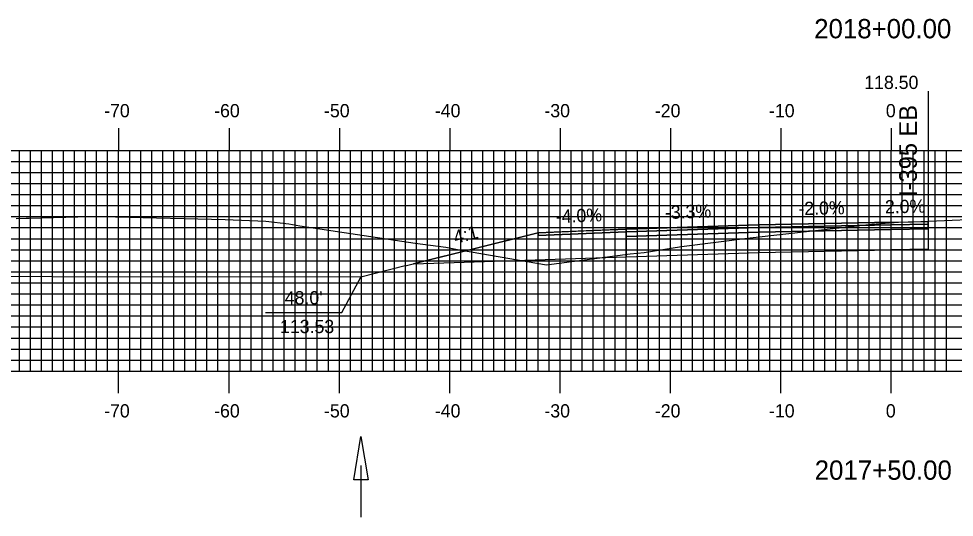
# Model space of a CAD drawing. Extents: x 855074 to 855418, y 366605 to 366825.
# Drawn here: x 855161 to 855245.8, y 366654.8 to 366700 of the extents above; entities that cross this region are included whole.
import ezdxf

# ---------------------------------------------------------------- set-up
doc = ezdxf.new("R2010")
doc.units = 0
for name, color, linetype in [('ANNOTATION', 7, 'Continuous'), ('D_Drainage_Ditch_Line', 7, 'Continuous'), ('D_Roadway_Centerline', 7, 'Continuous'), ('D_Roadway_Centerline_Text', 7, 'Continuous'), ('D_Roadway_Edge_Shoulder', 7, 'Continuous'), ('D_Roadway_Edge_TW', 7, 'Continuous'), ('D_Roadway_Pavement', 7, 'Continuous'), ('D_Roadway_SubGrade', 7, 'Continuous'), ('H_V ANNOTATION', 7, 'Continuous'), ('M_Roadway_Centerline', 7, 'Continuous'), ('MAJOR', 7, 'Continuous'), ('MINOR', 7, 'Continuous'), ('S_Roadway_Centerline', 7, 'Continuous')]:
    doc.layers.add(name, color=color, linetype=linetype)

msp = doc.modelspace()

# ---------------------------------------------------------------- linework, layer by layer
at = {"layer": 'ANNOTATION'}
msp.add_lwpolyline([(855183.363, 366673.373), (855190.292, 366673.373), (855192.022, 366676.583)], dxfattribs=at)
at = {"layer": 'D_Drainage_Ditch_Line'}
msp.add_line((855192.022, 366659.509), (855192.022, 366654.81), dxfattribs=at)
msp.add_lwpolyline([(855192.679, 366658.196), (855191.366, 366658.196), (855192.022, 366662.133)], close=True, dxfattribs=at)
at = {"layer": 'D_Roadway_Centerline'}
msp.add_lwpolyline([(855196.022, 366677.583), (855208.066, 366680.594), (855208.07, 366680.595), (855208.072, 366680.595), (855212.217, 366680.761), (855216.07, 366680.915), (855216.073, 366680.915), (855228.069, 366681.313), (855240.064, 366681.553), (855240.069, 366681.553), (855240.071, 366681.553), (855243.105, 366681.614), (855243.411, 366681.62)], dxfattribs=at)
at = {"layer": 'D_Roadway_Edge_Shoulder'}
for points in [[(855216.07, 366680.915), (855208.07, 366680.595), (855208.07, 366680.345), (855216.07, 366680.665)], [(855240.069, 366681.553), (855243.41, 366681.62), (855243.41, 366681.37), (855240.069, 366681.303)]]:
    msp.add_lwpolyline(points, close=True, dxfattribs=at)
at = {"layer": 'D_Roadway_Edge_TW'}
for points in [[(855228.069, 366681.313), (855216.07, 366680.915), (855216.07, 366680.665), (855228.069, 366681.063)], [(855240.069, 366681.553), (855228.069, 366681.313), (855228.069, 366681.063), (855240.069, 366681.303)]]:
    msp.add_lwpolyline(points, close=True, dxfattribs=at)
at = {"layer": 'D_Roadway_Pavement'}
for points in [[(855228.069, 366681.063), (855216.07, 366680.665), (855216.07, 366680.248), (855228.069, 366680.647)], [(855240.069, 366681.303), (855228.069, 366681.063), (855228.069, 366680.647), (855240.069, 366680.887)], [(855240.069, 366681.303), (855243.41, 366681.37), (855243.41, 366680.953), (855240.069, 366680.887)]]:
    msp.add_lwpolyline(points, close=True, dxfattribs=at)
for points in [[(855228.069, 366681.063), (855228.069, 366680.647)], [(855216.07, 366680.665), (855216.07, 366680.248)], [(855216.07, 366680.665), (855216.07, 366680.248)]]:
    msp.add_lwpolyline(points, dxfattribs=at)
at = {"layer": 'D_Roadway_SubGrade'}
msp.add_line((855243.41, 366693.429), (855243.41, 366679.12), dxfattribs=at)
for points in [[(855240.069, 366680.887), (855228.069, 366680.647), (855228.069, 366678.813), (855240.069, 366679.053)], [(855240.069, 366680.887), (855243.41, 366680.953), (855243.41, 366681.37), (855243.41, 366681.62), (855243.41, 366679.12), (855240.069, 366679.053)], [(855216.07, 366680.248), (855216.07, 366680.665), (855208.07, 366680.345), (855208.07, 366680.595), (855196.791, 366677.775), (855216.07, 366678.415)], [(855228.069, 366680.647), (855216.07, 366680.248), (855216.07, 366678.415), (855228.069, 366678.813)]]:
    msp.add_lwpolyline(points, close=True, dxfattribs=at)
msp.add_lwpolyline([(855196.022, 366677.583), (855192.022, 366676.583), (855108.208, 366676.667)], dxfattribs=at)
at = {"layer": 'MAJOR'}
for p, q in [((855170.069, 366690.059), (855170.069, 366688.055)), ((855180.069, 366690.059), (855180.069, 366688.055)), ((855190.069, 366690.059), (855190.069, 366688.055)), ((855200.069, 366690.059), (855200.069, 366688.055)), ((855210.069, 366690.059), (855210.069, 366688.055)), ((855220.069, 366690.059), (855220.069, 366688.055)), ((855230.069, 366690.059), (855230.069, 366688.055)), ((855240.069, 366690.059), (855240.069, 366688.055)), ((855100.069, 366688.055), (855380.069, 366688.055)), ((855100.069, 366688.055), (855380.069, 366688.055)), ((855170.069, 366668.055), (855170.069, 366688.055)), ((855180.069, 366668.055), (855180.069, 366688.055)), ((855190.069, 366668.055), (855190.069, 366688.055)), ((855200.069, 366668.055), (855200.069, 366688.055)), ((855210.069, 366668.055), (855210.069, 366688.055)), ((855220.069, 366668.055), (855220.069, 366688.055)), ((855230.069, 366668.055), (855230.069, 366688.055)), ((855240.069, 366668.055), (855240.069, 366688.055)), ((855100.069, 366683.055), (855380.069, 366683.055)), ((855100.069, 366678.055), (855380.069, 366678.055)), ((855100.069, 366673.055), (855380.069, 366673.055)), ((855100.069, 366668.055), (855380.069, 366668.055)), ((855100.069, 366668.055), (855380.069, 366668.055)), ((855170.069, 366666.051), (855170.069, 366668.055)), ((855180.069, 366666.051), (855180.069, 366668.055)), ((855190.069, 366666.051), (855190.069, 366668.055)), ((855200.069, 366666.051), (855200.069, 366668.055)), ((855210.069, 366666.051), (855210.069, 366668.055)), ((855220.069, 366666.051), (855220.069, 366668.055)), ((855230.069, 366666.051), (855230.069, 366668.055)), ((855240.069, 366666.051), (855240.069, 366668.055))]:
    msp.add_line(p, q, dxfattribs=at)
at = {"layer": 'MINOR'}
for p, q in [((855161.069, 366668.055), (855161.069, 366688.055)), ((855162.069, 366668.055), (855162.069, 366688.055)), ((855163.069, 366668.055), (855163.069, 366688.055)), ((855164.069, 366668.055), (855164.069, 366688.055)), ((855165.069, 366668.055), (855165.069, 366688.055)), ((855166.069, 366668.055), (855166.069, 366688.055)), ((855167.069, 366668.055), (855167.069, 366688.055)), ((855168.069, 366668.055), (855168.069, 366688.055)), ((855169.069, 366668.055), (855169.069, 366688.055)), ((855171.069, 366668.055), (855171.069, 366688.055)), ((855172.069, 366668.055), (855172.069, 366688.055)), ((855173.069, 366668.055), (855173.069, 366688.055)), ((855174.069, 366668.055), (855174.069, 366688.055)), ((855175.069, 366668.055), (855175.069, 366688.055)), ((855176.069, 366668.055), (855176.069, 366688.055)), ((855177.069, 366668.055), (855177.069, 366688.055)), ((855178.069, 366668.055), (855178.069, 366688.055)), ((855179.069, 366668.055), (855179.069, 366688.055)), ((855181.069, 366668.055), (855181.069, 366688.055)), ((855182.069, 366668.055), (855182.069, 366688.055)), ((855183.069, 366668.055), (855183.069, 366688.055)), ((855184.069, 366668.055), (855184.069, 366688.055)), ((855185.069, 366668.055), (855185.069, 366688.055)), ((855186.069, 366668.055), (855186.069, 366688.055)), ((855187.069, 366668.055), (855187.069, 366688.055)), ((855188.069, 366668.055), (855188.069, 366688.055)), ((855189.069, 366668.055), (855189.069, 366688.055)), ((855191.069, 366668.055), (855191.069, 366688.055)), ((855192.069, 366668.055), (855192.069, 366688.055)), ((855193.069, 366668.055), (855193.069, 366688.055)), ((855194.069, 366668.055), (855194.069, 366688.055)), ((855195.069, 366668.055), (855195.069, 366688.055)), ((855196.069, 366668.055), (855196.069, 366688.055)), ((855197.069, 366668.055), (855197.069, 366688.055)), ((855198.069, 366668.055), (855198.069, 366688.055)), ((855199.069, 366668.055), (855199.069, 366688.055)), ((855201.069, 366668.055), (855201.069, 366688.055)), ((855202.069, 366668.055), (855202.069, 366688.055)), ((855203.069, 366668.055), (855203.069, 366688.055)), ((855204.069, 366668.055), (855204.069, 366688.055)), ((855205.069, 366668.055), (855205.069, 366688.055)), ((855206.069, 366668.055), (855206.069, 366688.055)), ((855207.069, 366668.055), (855207.069, 366688.055)), ((855208.069, 366668.055), (855208.069, 366688.055)), ((855209.069, 366668.055), (855209.069, 366688.055)), ((855211.069, 366668.055), (855211.069, 366688.055)), ((855212.069, 366668.055), (855212.069, 366688.055)), ((855213.069, 366668.055), (855213.069, 366688.055)), ((855214.069, 366668.055), (855214.069, 366688.055)), ((855215.069, 366668.055), (855215.069, 366688.055)), ((855216.069, 366668.055), (855216.069, 366688.055)), ((855217.069, 366668.055), (855217.069, 366688.055)), ((855218.069, 366668.055), (855218.069, 366688.055)), ((855219.069, 366668.055), (855219.069, 366688.055)), ((855221.069, 366668.055), (855221.069, 366688.055)), ((855222.069, 366668.055), (855222.069, 366688.055)), ((855223.069, 366668.055), (855223.069, 366688.055)), ((855224.069, 366668.055), (855224.069, 366688.055)), ((855225.069, 366668.055), (855225.069, 366688.055)), ((855226.069, 366668.055), (855226.069, 366688.055)), ((855227.069, 366668.055), (855227.069, 366688.055)), ((855228.069, 366668.055), (855228.069, 366688.055)), ((855229.069, 366668.055), (855229.069, 366688.055)), ((855231.069, 366668.055), (855231.069, 366688.055)), ((855232.069, 366668.055), (855232.069, 366688.055)), ((855233.069, 366668.055), (855233.069, 366688.055)), ((855234.069, 366668.055), (855234.069, 366688.055)), ((855235.069, 366668.055), (855235.069, 366688.055)), ((855236.069, 366668.055), (855236.069, 366688.055)), ((855237.069, 366668.055), (855237.069, 366688.055)), ((855238.069, 366668.055), (855238.069, 366688.055)), ((855239.069, 366668.055), (855239.069, 366688.055)), ((855241.069, 366668.055), (855241.069, 366688.055)), ((855242.069, 366668.055), (855242.069, 366688.055)), ((855243.069, 366668.055), (855243.069, 366688.055)), ((855244.069, 366668.055), (855244.069, 366688.055)), ((855245.069, 366668.055), (855245.069, 366688.055)), ((855100.069, 366687.055), (855380.069, 366687.055)), ((855100.069, 366686.055), (855380.069, 366686.055)), ((855100.069, 366685.055), (855380.069, 366685.055)), ((855100.069, 366684.055), (855380.069, 366684.055)), ((855100.069, 366682.055), (855380.069, 366682.055)), ((855100.069, 366681.055), (855380.069, 366681.055)), ((855100.069, 366680.055), (855380.069, 366680.055)), ((855100.069, 366679.055), (855380.069, 366679.055)), ((855100.069, 366677.055), (855380.069, 366677.055)), ((855100.069, 366676.055), (855380.069, 366676.055)), ((855100.069, 366675.055), (855380.069, 366675.055)), ((855100.069, 366674.055), (855380.069, 366674.055)), ((855100.069, 366672.055), (855380.069, 366672.055)), ((855100.069, 366671.055), (855380.069, 366671.055)), ((855100.069, 366670.055), (855380.069, 366670.055)), ((855100.069, 366669.055), (855380.069, 366669.055))]:
    msp.add_line(p, q, dxfattribs=at)
at = {"layer": 'S_Roadway_Centerline'}
msp.add_lwpolyline([(855160.783, 366681.879), (855161.681, 366681.921), (855161.954, 366681.929), (855167.481, 366682.055), (855167.588, 366682.057), (855169.774, 366682.028), (855179.724, 366681.791), (855183.4, 366681.654), (855185.504, 366681.387), (855186.499, 366681.222), (855196.928, 366679.661), (855199.726, 366679.28), (855201.064, 366679.008), (855201.15, 366679.012), (855208.834, 366677.69), (855216.431, 366678.693), (855217.678, 366678.793), (855221.085, 366679.344), (855227.293, 366680.131), (855238.32, 366681.372), (855240.731, 366681.554), (855242.055, 366681.596), (855250.542, 366681.959)], dxfattribs=at)

# ---------------------------------------------------------------- texts
at = {"layer": 'ANNOTATION'}
for s, height, rotation, p in [('I-395 EB', 1.6, 90, (855242.397, 366683.847)), ('-2.0%', 1.2, 1.14576, (855231.673, 366682.186)), ('2.0%', 1.2, 1.14885, (855239.515, 366682.343)), ('-4.0%', 1.2, 2.29059, (855209.703, 366681.462)), ('-3.3%', 1.2, 1.89965, (855219.588, 366681.833)), ('4:1', 1.2, 14.03701, (855200.58, 366679.584)), ("48.0' ", 1.2, 360, (855185.119, 366674.099)), ('113.53', 1.2, 360, (855184.691, 366671.499))]:
    msp.add_text(s, height=height, rotation=rotation, dxfattribs=at).set_placement(p)
at = {"layer": 'D_Roadway_Centerline_Text'}
msp.add_text('118.50', height=1.2, dxfattribs=at).set_placement((855237.629, 366693.619))
at = {"layer": 'H_V ANNOTATION'}
for s, height, p in [('2018+00.00', 1.75, (855233.093, 366698.211)), ('-70', 1.2, (855168.753, 366691.055)), ('-60', 1.2, (855178.721, 366691.055)), ('-50', 1.2, (855188.678, 366691.055)), ('-40', 1.2, (855198.721, 366691.055)), ('-30', 1.2, (855208.646, 366691.055)), ('-20', 1.2, (855218.656, 366691.055)), ('-10', 1.2, (855228.999, 366691.055)), ('0', 1.2, (855239.588, 366691.055)), ('-70', 1.2, (855168.753, 366663.855)), ('-60', 1.2, (855178.721, 366663.855)), ('-50', 1.2, (855188.678, 366663.855)), ('-40', 1.2, (855198.721, 366663.855)), ('-30', 1.2, (855208.646, 366663.855)), ('-20', 1.2, (855218.656, 366663.855)), ('-10', 1.2, (855228.999, 366663.855)), ('0', 1.2, (855239.588, 366663.855)), ('2017+50.00', 1.75, (855233.14, 366658.211))]:
    msp.add_text(s, height=height, dxfattribs=at).set_placement(p)
at = {"layer": 'M_Roadway_Centerline'}
for s, p in [('C', (855167.583, 366682.057)), ('L', (855167.588, 366682.05))]:
    msp.add_text(s, height=0.0146, dxfattribs=at).set_placement(p)

doc.saveas('drawing.dxf')
